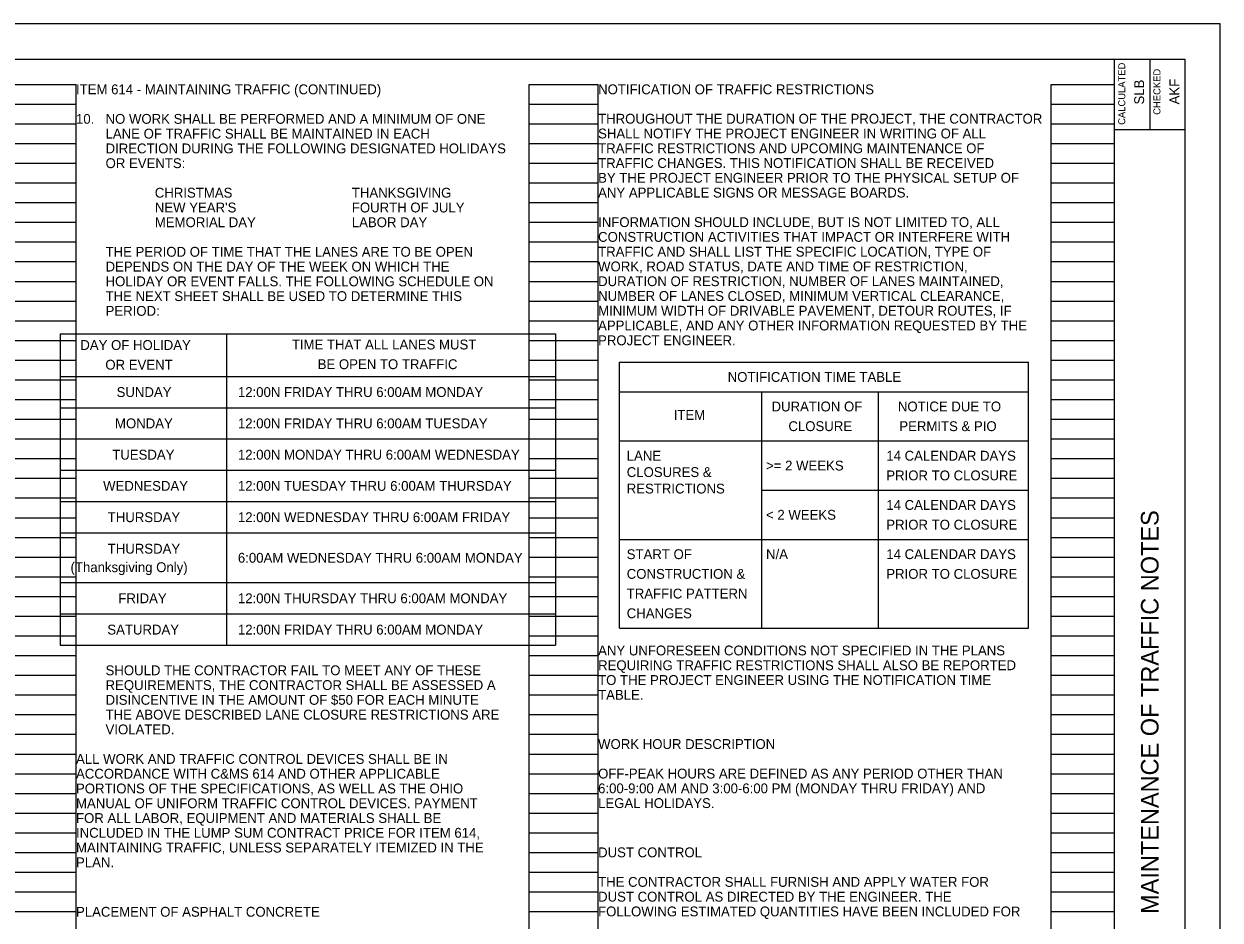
# Model space of a CAD drawing. Extents: x -16.4 to 17.6, y -12.9 to 9.1.
# Drawn here: x 0.63 to 17.63, y -3.65 to 9.09 of the extents above; entities that cross this region are included whole.
import ezdxf

# ---------------------------------------------------------------- set-up
doc = ezdxf.new("R2010")
doc.units = 0
for name, color, linetype in [('SH_Border', 7, 'Continuous'), ('SH_Cut_Line', 7, 'Continuous'), ('SH_Data', 7, 'Continuous'), ('SH_Text', 7, 'Continuous'), ('TX_P_1', 7, 'Continuous'), ('TX_P_5', 7, 'Continuous'), ('TX_P_50', 7, 'Continuous')]:
    doc.layers.add(name, color=color, linetype=linetype)

# ---------------------------------------------------------------- blocks, each defined once
blk = doc.blocks.new('4COL')
at = {"layer": 'SH_Data'}
for p, q in [((16.76, 21.14), (17.74, 21.14)), ((17.74, 0.98), (17.74, 21.14)), ((24.18, 0.98), (24.18, 21.14)), ((24.18, 21.14), (25.16, 21.14)), ((25.16, 0.98), (25.16, 21.14)), ((31.6, 0.98), (31.6, 21.14)), ((31.6, 21.14), (32.5, 21.14)), ((32.5, 0.98), (32.5, 21.14)), ((16.76, 20.86), (17.74, 20.86)), ((24.18, 20.86), (25.16, 20.86)), ((31.6, 20.86), (32.5, 20.86)), ((16.76, 20.58), (17.74, 20.58)), ((24.18, 20.58), (25.16, 20.58)), ((31.6, 20.58), (32.5, 20.58)), ((16.76, 20.3), (17.74, 20.3)), ((24.18, 20.3), (25.16, 20.3)), ((31.6, 20.3), (32.5, 20.3)), ((16.76, 20.02), (17.74, 20.02)), ((24.18, 20.02), (25.16, 20.02)), ((31.6, 20.02), (32.5, 20.02)), ((16.76, 19.74), (17.74, 19.74)), ((24.18, 19.74), (25.16, 19.74)), ((31.6, 19.74), (32.5, 19.74)), ((16.76, 19.46), (17.74, 19.46)), ((24.18, 19.46), (25.16, 19.46)), ((31.6, 19.46), (32.5, 19.46)), ((16.76, 19.18), (17.74, 19.18)), ((24.18, 19.18), (25.16, 19.18)), ((31.6, 19.18), (32.5, 19.18)), ((16.76, 18.9), (17.74, 18.9)), ((24.18, 18.9), (25.16, 18.9)), ((31.6, 18.9), (32.5, 18.9)), ((16.76, 18.62), (17.74, 18.62)), ((24.18, 18.62), (25.16, 18.62)), ((31.6, 18.62), (32.5, 18.62)), ((16.76, 18.34), (17.74, 18.34)), ((24.18, 18.34), (25.16, 18.34)), ((31.6, 18.34), (32.5, 18.34)), ((16.76, 18.06), (17.74, 18.06)), ((24.18, 18.06), (25.16, 18.06)), ((31.6, 18.06), (32.5, 18.06)), ((16.76, 17.78), (17.74, 17.78)), ((24.18, 17.78), (25.16, 17.78)), ((31.6, 17.78), (32.5, 17.78)), ((16.76, 17.5), (17.74, 17.5)), ((24.18, 17.5), (25.16, 17.5)), ((31.6, 17.5), (32.5, 17.5)), ((16.76, 17.22), (17.74, 17.22)), ((24.18, 17.22), (25.16, 17.22)), ((31.6, 17.22), (32.5, 17.22)), ((16.76, 16.94), (17.74, 16.94)), ((24.18, 16.94), (25.16, 16.94)), ((31.6, 16.94), (32.5, 16.94)), ((16.76, 16.66), (17.74, 16.66)), ((24.18, 16.66), (25.16, 16.66)), ((31.6, 16.66), (32.5, 16.66)), ((16.76, 16.38), (17.74, 16.38)), ((24.18, 16.38), (25.16, 16.38)), ((31.6, 16.38), (32.5, 16.38)), ((16.76, 16.1), (17.74, 16.1)), ((24.18, 16.1), (25.16, 16.1)), ((31.6, 16.1), (32.5, 16.1)), ((16.76, 15.82), (17.74, 15.82)), ((24.18, 15.82), (25.16, 15.82)), ((31.6, 15.82), (32.5, 15.82)), ((16.76, 15.54), (17.74, 15.54)), ((24.18, 15.54), (25.16, 15.54)), ((31.6, 15.54), (32.5, 15.54)), ((16.76, 15.26), (17.74, 15.26)), ((24.18, 15.26), (25.16, 15.26)), ((31.6, 15.26), (32.5, 15.26)), ((16.76, 14.98), (17.74, 14.98)), ((24.18, 14.98), (25.16, 14.98)), ((31.6, 14.98), (32.5, 14.98)), ((16.76, 14.7), (17.74, 14.7)), ((24.18, 14.7), (25.16, 14.7)), ((31.6, 14.7), (32.5, 14.7)), ((16.76, 14.42), (17.74, 14.42)), ((24.18, 14.42), (25.16, 14.42)), ((31.6, 14.42), (32.5, 14.42)), ((16.76, 14.14), (17.74, 14.14)), ((24.18, 14.14), (25.16, 14.14)), ((31.6, 14.14), (32.5, 14.14)), ((16.76, 13.86), (17.74, 13.86)), ((24.18, 13.86), (25.16, 13.86)), ((31.6, 13.86), (32.5, 13.86)), ((16.76, 13.58), (17.74, 13.58)), ((24.18, 13.58), (25.16, 13.58)), ((31.6, 13.58), (32.5, 13.58)), ((16.76, 13.3), (17.74, 13.3)), ((24.18, 13.3), (25.16, 13.3)), ((31.6, 13.3), (32.5, 13.3)), ((16.76, 13.02), (17.74, 13.02)), ((24.18, 13.02), (25.16, 13.02)), ((31.6, 13.02), (32.5, 13.02)), ((16.76, 12.74), (17.74, 12.74)), ((24.18, 12.74), (25.16, 12.74)), ((31.6, 12.74), (32.5, 12.74)), ((16.76, 12.46), (17.74, 12.46)), ((24.18, 12.46), (25.16, 12.46)), ((31.6, 12.46), (32.5, 12.46)), ((16.76, 12.18), (17.74, 12.18)), ((24.18, 12.18), (25.16, 12.18)), ((31.6, 12.18), (32.5, 12.18)), ((16.76, 11.9), (17.74, 11.9)), ((24.18, 11.9), (25.16, 11.9)), ((31.6, 11.9), (32.5, 11.9)), ((16.76, 11.62), (17.74, 11.62)), ((24.18, 11.62), (25.16, 11.62)), ((31.6, 11.62), (32.5, 11.62)), ((16.76, 11.34), (17.74, 11.34)), ((24.18, 11.34), (25.16, 11.34)), ((31.6, 11.34), (32.5, 11.34)), ((16.76, 11.06), (17.74, 11.06)), ((24.18, 11.06), (25.16, 11.06)), ((31.6, 11.06), (32.5, 11.06)), ((16.76, 10.78), (17.74, 10.78)), ((24.18, 10.78), (25.16, 10.78)), ((31.6, 10.78), (32.5, 10.78)), ((16.76, 10.5), (17.74, 10.5)), ((24.18, 10.5), (25.16, 10.5)), ((31.6, 10.5), (32.5, 10.5)), ((16.76, 10.22), (17.74, 10.22)), ((24.18, 10.22), (25.16, 10.22)), ((31.6, 10.22), (32.5, 10.22)), ((16.76, 9.94), (17.74, 9.94)), ((24.18, 9.94), (25.16, 9.94)), ((31.6, 9.94), (32.5, 9.94)), ((16.76, 9.66), (17.74, 9.66)), ((24.18, 9.66), (25.16, 9.66)), ((31.6, 9.66), (32.5, 9.66)), ((16.76, 9.38), (17.74, 9.38)), ((24.18, 9.38), (25.16, 9.38)), ((31.6, 9.38), (32.5, 9.38))]:
    blk.add_line(p, q, dxfattribs=at)

msp = doc.modelspace()

# ---------------------------------------------------------------- linework, layer by layer
at = {"layer": 'SH_Border'}
for p, q in [((16.129, -12.407), (16.129, 8.593)), ((16.629, 8.593), (16.629, 7.593)), ((16.129, 7.593), (17.129, 7.593))]:
    msp.add_line(p, q, dxfattribs=at)
msp.add_lwpolyline([(-14.371, 8.593), (17.129, 8.593), (17.129, -12.407), (-14.371, -12.407)], close=True, dxfattribs=at)
at = {"layer": 'SH_Cut_Line'}
msp.add_lwpolyline([(-16.371, -12.907), (17.629, -12.907), (17.629, 9.093), (-16.371, 9.093)], close=True, dxfattribs=at)
at = {"layer": 'SH_Text'}
for p, q in [((1.143, 4.688), (8.182, 4.688)), ((1.143, 4.688), (1.143, 0.26)), ((3.508, 4.688), (3.508, 0.26)), ((8.182, 4.688), (8.182, 0.26)), ((9.091, 4.284), (14.906, 4.284)), ((9.091, 0.504), (9.091, 4.284)), ((14.906, 0.504), (14.906, 4.284)), ((1.143, 4.082), (8.182, 4.082)), ((9.091, 3.864), (14.906, 3.864)), ((11.109, 3.864), (11.109, 0.504)), ((12.771, 3.864), (12.771, 0.504)), ((1.143, 3.637), (8.182, 3.637)), ((1.143, 3.192), (8.182, 3.192)), ((9.091, 3.164), (14.906, 3.164)), ((1.143, 2.747), (8.182, 2.747)), ((11.109, 2.464), (14.906, 2.464)), ((1.143, 2.302), (8.182, 2.302)), ((1.143, 1.857), (8.182, 1.857)), ((9.091, 1.764), (14.906, 1.764)), ((1.143, 1.15), (8.182, 1.15)), ((1.143, 0.705), (8.182, 0.705)), ((9.091, 0.504), (14.906, 0.504)), ((1.143, 0.26), (8.182, 0.26))]:
    msp.add_line(p, q, dxfattribs=at)

# ---------------------------------------------------------------- block references
msp.add_blockref('4COL', (-16.371, -12.907), dxfattribs=at)

# ---------------------------------------------------------------- texts
at = {"layer": 'SH_Data'}
for s, height, p in [('CALCULATED', 0.1, (16.281, 7.658)), ('CHECKED', 0.1, (16.781, 7.801)), ('SLB', 0.14, (16.549, 7.947)), ('AKF', 0.14, (17.049, 7.949)), ('MAINTENANCE OF TRAFFIC NOTES', 0.25, (16.754, -3.56))]:
    msp.add_text(s, height=height, rotation=90, dxfattribs=at).set_placement(p)
at = {"layer": 'SH_Text'}
for s, p in [('ITEM 614 - MAINTAINING TRAFFIC (CONTINUED)', (1.369, 8.093)), ('NOTIFICATION OF TRAFFIC RESTRICTIONS', (8.789, 8.093)), ('10.', (1.369, 7.673)), ('NO WORK SHALL BE PERFORMED AND A MINIMUM OF ONE ', (1.789, 7.673)), ('THROUGHOUT THE DURATION OF THE PROJECT, THE CONTRACTOR ', (8.789, 7.675)), ('LANE OF TRAFFIC SHALL BE MAINTAINED IN EACH ', (1.789, 7.463)), ('SHALL NOTIFY THE PROJECT ENGINEER IN WRITING OF ALL ', (8.789, 7.465)), ('DIRECTION DURING THE FOLLOWING DESIGNATED HOLIDAYS ', (1.789, 7.253)), ('TRAFFIC RESTRICTIONS AND UPCOMING MAINTENANCE OF ', (8.789, 7.255)), ('OR EVENTS:', (1.789, 7.043)), ('TRAFFIC CHANGES. THIS NOTIFICATION SHALL BE RECEIVED ', (8.789, 7.045)), ('BY THE PROJECT ENGINEER PRIOR TO THE PHYSICAL SETUP OF ', (8.789, 6.835)), ('CHRISTMAS', (2.489, 6.623)), ('THANKSGIVING', (5.289, 6.623)), ('ANY APPLICABLE SIGNS OR MESSAGE BOARDS.', (8.789, 6.625)), ("NEW YEAR'S", (2.489, 6.413)), ('FOURTH OF JULY', (5.289, 6.413)), ('MEMORIAL DAY', (2.489, 6.203)), ('LABOR DAY', (5.289, 6.203)), ('INFORMATION SHOULD INCLUDE, BUT IS NOT LIMITED TO, ALL ', (8.789, 6.205)), ('CONSTRUCTION ACTIVITIES THAT IMPACT OR INTERFERE WITH ', (8.789, 5.995)), ('THE PERIOD OF TIME THAT THE LANES ARE TO BE OPEN ', (1.789, 5.783)), ('TRAFFIC AND SHALL LIST THE SPECIFIC LOCATION, TYPE OF ', (8.789, 5.785)), ('DEPENDS ON THE DAY OF THE WEEK ON WHICH THE ', (1.789, 5.573)), ('WORK, ROAD STATUS, DATE AND TIME OF RESTRICTION, ', (8.789, 5.575)), ('HOLIDAY OR EVENT FALLS. THE FOLLOWING SCHEDULE ON ', (1.789, 5.363)), ('DURATION OF RESTRICTION, NUMBER OF LANES MAINTAINED, ', (8.789, 5.365)), ('THE NEXT SHEET SHALL BE USED TO DETERMINE THIS ', (1.789, 5.153)), ('NUMBER OF LANES CLOSED, MINIMUM VERTICAL CLEARANCE, ', (8.789, 5.155)), ('PERIOD:', (1.789, 4.943)), ('MINIMUM WIDTH OF DRIVABLE PAVEMENT, DETOUR ROUTES, IF ', (8.789, 4.945)), ('APPLICABLE, AND ANY OTHER INFORMATION REQUESTED BY THE ', (8.789, 4.735)), ('PROJECT ENGINEER.', (8.789, 4.525)), ('ITEM ', (9.864, 3.463)), ('DURATION OF', (11.254, 3.584)), ('NOTICE DUE TO', (13.05, 3.584)), ('CLOSURE', (11.494, 3.304)), ('PERMITS & PIO', (13.07, 3.304)), ('LANE', (9.196, 2.884)), ('14 CALENDAR DAYS', (12.885, 2.884)), ('CLOSURES &', (9.196, 2.651)), ('>= 2 WEEKS', (11.176, 2.744)), ('PRIOR TO CLOSURE', (12.885, 2.604)), ('RESTRICTIONS', (9.196, 2.417)), ('14 CALENDAR DAYS', (12.885, 2.184)), ('< 2 WEEKS', (11.176, 2.044)), ('PRIOR TO CLOSURE', (12.885, 1.904)), ('START OF', (9.196, 1.484)), ('N/A', (11.176, 1.484)), ('14 CALENDAR DAYS', (12.885, 1.484)), ('CONSTRUCTION &', (9.196, 1.204)), ('PRIOR TO CLOSURE', (12.885, 1.204)), ('TRAFFIC PATTERN', (9.196, 0.924)), ('CHANGES', (9.196, 0.644)), ('ANY UNFORESEEN CONDITIONS NOT SPECIFIED IN THE PLANS ', (8.789, 0.115)), ('REQUIRING TRAFFIC RESTRICTIONS SHALL ALSO BE REPORTED ', (8.789, -0.095)), ('SHOULD THE CONTRACTOR FAIL TO MEET ANY OF THESE ', (1.789, -0.167)), ('TO THE PROJECT ENGINEER USING THE NOTIFICATION TIME ', (8.789, -0.305)), ('REQUIREMENTS, THE CONTRACTOR SHALL BE ASSESSED A ', (1.789, -0.377)), ('DISINCENTIVE IN THE AMOUNT OF $50 FOR EACH MINUTE ', (1.789, -0.587)), ('TABLE.', (8.789, -0.515)), ('THE ABOVE DESCRIBED LANE CLOSURE RESTRICTIONS ARE ', (1.789, -0.797)), ('VIOLATED.', (1.789, -1.007)), ('ALL WORK AND TRAFFIC CONTROL DEVICES SHALL BE IN ', (1.369, -1.427)), ('ACCORDANCE WITH C&MS 614 AND OTHER APPLICABLE ', (1.369, -1.637)), ('OFF-PEAK HOURS ARE DEFINED AS ANY PERIOD OTHER THAN ', (8.789, -1.635)), ('6:00-9:00 AM AND 3:00-6:00 PM (MONDAY THRU FRIDAY) AND ', (8.789, -1.845)), ('PORTIONS OF THE SPECIFICATIONS, AS WELL AS THE OHIO ', (1.369, -1.847)), ('MANUAL OF UNIFORM TRAFFIC CONTROL DEVICES. PAYMENT ', (1.369, -2.057)), ('LEGAL HOLIDAYS.', (8.789, -2.055)), ('FOR ALL LABOR, EQUIPMENT AND MATERIALS SHALL BE ', (1.369, -2.267)), ('INCLUDED IN THE LUMP SUM CONTRACT PRICE FOR ITEM 614, ', (1.369, -2.477)), ('MAINTAINING TRAFFIC, UNLESS SEPARATELY ITEMIZED IN THE ', (1.369, -2.687)), ('PLAN. ', (1.369, -2.897)), ('THE CONTRACTOR SHALL FURNISH AND APPLY WATER FOR ', (8.789, -3.175)), ('DUST CONTROL AS DIRECTED BY THE ENGINEER. THE ', (8.789, -3.385)), ('FOLLOWING ESTIMATED QUANTITIES HAVE BEEN INCLUDED FOR ', (8.789, -3.595))]:
    msp.add_text(s, height=0.14, dxfattribs=at).set_placement(p)
at = {"layer": 'TX_P_1'}
for s, p in [('WORK HOUR DESCRIPTION', (8.789, -1.215)), ('DUST CONTROL', (8.789, -2.755)), ('PLACEMENT OF ASPHALT CONCRETE', (1.369, -3.6))]:
    msp.add_text(s, height=0.14, dxfattribs=at).set_placement(p)
at = {"layer": 'TX_P_5'}
msp.add_text('NOTIFICATION TIME TABLE', height=0.14, dxfattribs=at).set_placement((10.631, 4.004))
at = {"layer": 'TX_P_50'}
for s, p in [('DAY OF HOLIDAY ', (1.43, 4.458)), ('TIME THAT ALL LANES MUST ', (4.437, 4.465)), ('OR EVENT', (1.786, 4.178)), ('BE OPEN TO TRAFFIC', (4.804, 4.185)), ('SUNDAY', (1.946, 3.789)), ('12:00N FRIDAY THRU 6:00AM MONDAY', (3.67, 3.789)), ('MONDAY', (1.923, 3.344)), ('12:00N FRIDAY THRU 6:00AM TUESDAY', (3.67, 3.344)), ('TUESDAY', (1.884, 2.899)), ('12:00N MONDAY THRU 6:00AM WEDNESDAY', (3.67, 2.899)), ('WEDNESDAY', (1.754, 2.455)), ('12:00N TUESDAY THRU 6:00AM THURSDAY', (3.67, 2.455)), ('THURSDAY', (1.82, 2.01)), ('12:00N WEDNESDAY THRU 6:00AM FRIDAY', (3.67, 2.01)), ('THURSDAY', (1.82, 1.562)), ('6:00AM WEDNESDAY THRU 6:00AM MONDAY', (3.67, 1.433)), ('(Thanksgiving Only)', (1.291, 1.299)), ('FRIDAY', (1.971, 0.857)), ('12:00N THURSDAY THRU 6:00AM MONDAY', (3.67, 0.857)), ('SATURDAY', (1.814, 0.412)), ('12:00N FRIDAY THRU 6:00AM MONDAY', (3.67, 0.412))]:
    msp.add_text(s, height=0.14, dxfattribs=at).set_placement(p)

doc.saveas('drawing.dxf')
